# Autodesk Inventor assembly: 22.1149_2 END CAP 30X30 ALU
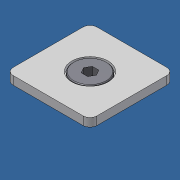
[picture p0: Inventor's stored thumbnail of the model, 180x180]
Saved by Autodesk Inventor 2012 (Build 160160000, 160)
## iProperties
Created: 2014-04
Part Number: 22.1149_2 END CAP 30X30 ALU
Document SubType Name: Assembly
Designer: Admin
Author: Admin
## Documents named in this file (3)
- C:\Andys Backup Data\ANDY'S INVENTOR\INVENTOR LIBRARIES\PARTS LIBRARY\30 SERIES\22.1149_2 END CAP 30X30 ALU.iam
- C:\Andys Backup Data\ANDY'S INVENTOR\INVENTOR LIBRARIES\PARTS LIBRARY\30 SERIES\SUBCOMPONENTS\22.1149_2 CAP 30X30 ALU NO SCREW.ipt
- C:\Andys Backup Data\ANDY'S INVENTOR\INVENTOR LIBRARIES\PARTS LIBRARY\FASTENING ELEMENTS\SCREWS CAP STAINLESS\21.1666 M8x10 Stainless.ipt
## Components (2 placed, 2 different names)
1. 22.1149_2 CAP 30X30 ALU NO SCREW:1 — Insert:1
2. 21.1666 M8x10 Stainless ELH:1 — Insert:1
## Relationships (1: Insert 1)
- Insert:1: 22.1149_2 CAP 30X30 ALU NO SCREW:1 ↔ 21.1666 M8x10 Stainless ELH:1
